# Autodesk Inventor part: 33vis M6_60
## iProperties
Created: 2011-01
Part Number: 33vis M6_60
Document SubType Name: Modeling
Designer: eric
Density: 1 g/cm^3
Mass: 2.06284 g
Surface Area: 15.3346 cm^2
Volume: 2.06284 cm^3
Author: eric
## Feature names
1. Base1
